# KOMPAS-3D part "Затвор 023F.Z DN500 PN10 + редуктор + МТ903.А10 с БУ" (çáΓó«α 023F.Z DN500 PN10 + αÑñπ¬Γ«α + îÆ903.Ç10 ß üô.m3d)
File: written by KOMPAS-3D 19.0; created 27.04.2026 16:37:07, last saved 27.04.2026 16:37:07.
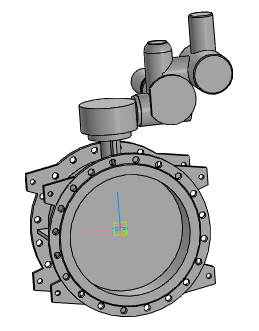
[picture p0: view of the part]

Document properties: Полное имя файла: ..\..\Затвор 023F.Z DN400-DN1600 + редуктор + МТ903\Затвор 023F.Z DN500 PN10 + редуктор + МТ903.А10 с БУ.a3d

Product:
- Part/product: Затвор 023F.Z DN500 PN10 + редуктор + МТ903.А10 с БУ
    Масса: 385.453

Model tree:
1. Операция без истории:1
